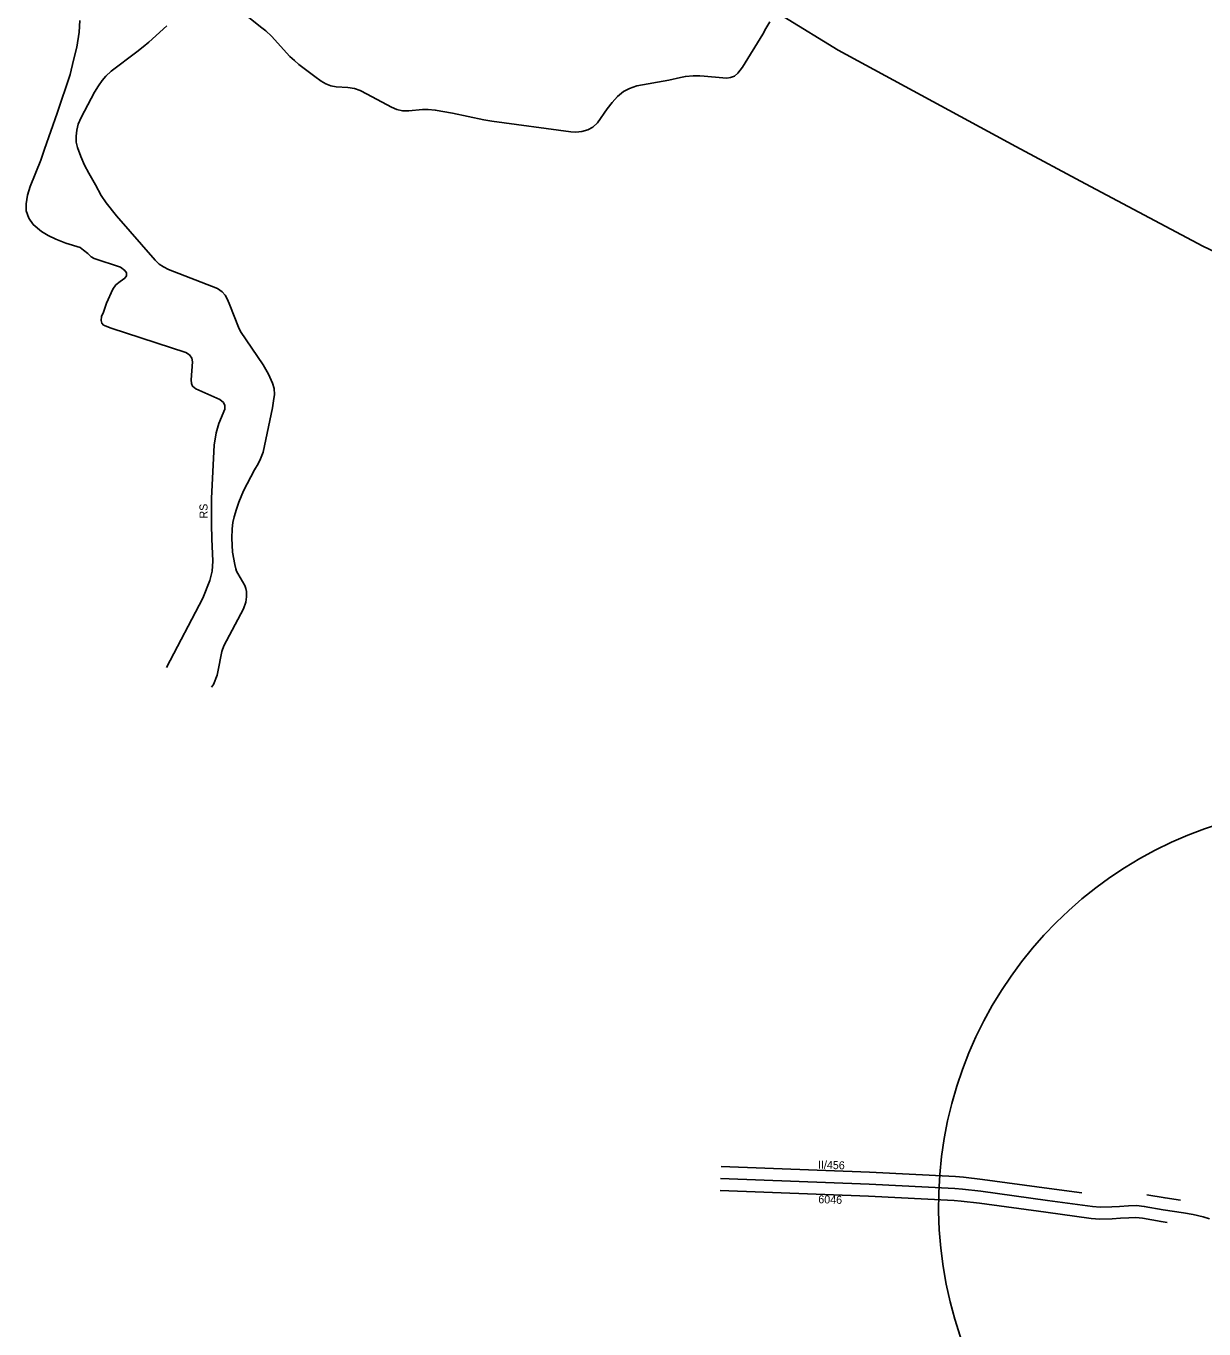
# Model space of a CAD drawing. Extents: x -546703 to -534152, y -1046534 to -1035676.
# Drawn here: x -545023 to -543551, y -1040697 to -1039069 of the extents above; entities that cross this region are included whole.
import ezdxf

# ---------------------------------------------------------------- set-up
doc = ezdxf.new("R2010")
doc.units = 0
for name, color, linetype in [('Vrstva 11', 7, 'Continuous'), ('Vrstva 17', 7, 'Continuous'), ('Vrstva 22', 7, 'Continuous'), ('Vrstva 26', 7, 'Continuous'), ('Vrstva 3', 7, 'Continuous')]:
    doc.layers.add(name, color=color, linetype=linetype)

msp = doc.modelspace()

# ---------------------------------------------------------------- linework, layer by layer
at = {"layer": 'Vrstva 11'}
for points in [[(-544093.2, -1039063.3), (-544098.2, -1039071.8), (-544102, -1039078.9), (-544127.3, -1039120.2), (-544133.1, -1039127.7), (-544137.4, -1039131.3), (-544142.2, -1039133.1), (-544147.1, -1039133.8), (-544151.9, -1039133.5), (-544175.2, -1039131.2), (-544180.8, -1039130.9), (-544189.2, -1039131), (-544198.6, -1039131.7), (-544204.8, -1039132.9), (-544219.4, -1039136.2), (-544259.5, -1039143.5), (-544268.4, -1039146.6), (-544275.9, -1039150.7), (-544283.5, -1039156.9), (-544290.2, -1039164.3), (-544296.6, -1039172.3), (-544308.6, -1039189.6), (-544314.3, -1039195), (-544320.5, -1039198.5), (-544328.2, -1039200.7), (-544335.6, -1039201.2), (-544342, -1039200.8), (-544440.4, -1039187.8), (-544450.4, -1039186), (-544489.5, -1039177.8), (-544511.2, -1039173.8), (-544519.9, -1039173), (-544527.3, -1039173.2), (-544544.2, -1039174.8), (-544552.1, -1039174.6), (-544559.3, -1039172.9), (-544565.9, -1039170.3), (-544596.2, -1039154), (-544605.1, -1039149.4), (-544612, -1039146.9), (-544620.5, -1039145.6), (-544634.9, -1039144.8), (-544641.6, -1039143.3), (-544648.1, -1039140.8), (-544654, -1039137.7), (-544661.6, -1039132), (-544681.6, -1039116.9), (-544687, -1039112), (-544693.1, -1039106.7), (-544715.9, -1039081.6), (-544723.1, -1039074.8), (-544729.4, -1039069.9), (-544784.9, -1039024.7)], [(-543511.8, -1039362.9), (-543552.3, -1039343.9), (-543698.9, -1039265.8), (-543785.9, -1039219.3), (-544008, -1039098.7), (-544075.9, -1039057.3)], [(-544846.8, -1039068.5), (-544869.2, -1039089), (-544876.1, -1039094.9), (-544884.3, -1039100.9), (-544916, -1039125.1), (-544922.7, -1039131.3), (-544927.6, -1039136.9), (-544932.2, -1039143.6), (-544936.8, -1039151.5), (-544953.8, -1039182.9), (-544957.4, -1039191.2), (-544959.2, -1039199), (-544959.9, -1039206.5), (-544959.8, -1039214), (-544958.4, -1039220.6), (-544953.9, -1039231.8), (-544949.3, -1039242.4), (-544944, -1039252.4), (-544935.9, -1039267.2), (-544928.5, -1039280.4), (-544922.4, -1039289.5), (-544909.5, -1039306), (-544861.2, -1039361.4), (-544856.2, -1039366.1), (-544850.7, -1039369.7), (-544844.4, -1039372.8), (-544783.3, -1039396.8), (-544777.5, -1039400.7), (-544773.8, -1039405.2), (-544770.8, -1039410.6), (-544767.8, -1039417.6), (-544757.1, -1039444.8), (-544754.7, -1039450.6), (-544747.7, -1039460.8), (-544726.1, -1039491.9), (-544719.6, -1039503.7), (-544714.4, -1039515), (-544712.4, -1039521.6), (-544712.2, -1039528.9), (-544713.5, -1039537.2), (-544714.8, -1039545.6), (-544726.2, -1039601.2), (-544729.7, -1039609.5), (-544732.7, -1039615.8), (-544736.9, -1039623.4), (-544750.8, -1039649.3), (-544756.5, -1039663.7), (-544759.7, -1039672.5), (-544762.7, -1039681.9), (-544764.2, -1039688.9), (-544764.9, -1039697), (-544765.2, -1039708.5), (-544764.7, -1039726.2), (-544761.7, -1039741.4), (-544760.6, -1039746.9), (-544759.5, -1039749.9), (-544758, -1039752.8), (-544749, -1039767.7), (-544747.8, -1039771.4), (-544747.2, -1039775.2), (-544747.2, -1039781.7), (-544748, -1039788.5), (-544750.9, -1039796.7), (-544775.4, -1039843.1), (-544778.1, -1039850.1), (-544782.9, -1039875.6), (-544783.6, -1039879.6), (-544788.5, -1039891.4), (-544790.7, -1039894.8)]]:
    msp.add_lwpolyline(points, dxfattribs=at)
at = {"layer": 'Vrstva 17'}
for points in [[(-544154.2, -1040493.6), (-543968.6, -1040500.9), (-543861.1, -1040506.2), (-543851.1, -1040506.9), (-543827.6, -1040509.7), (-543744.3, -1040521.1), (-543703.5, -1040526.7)], [(-543596.7, -1040563.7), (-543604.3, -1040562.5), (-543627.6, -1040558.4), (-543635.8, -1040557.4), (-543644.6, -1040557.6), (-543655.3, -1040558.4), (-543665.4, -1040559.1), (-543680.9, -1040559.3), (-543691.7, -1040558.6), (-543748.4, -1040550.8), (-543831.4, -1040539.4), (-543854, -1040536.8), (-543863, -1040536.1), (-543969.9, -1040530.9), (-544155.4, -1040523.5)], [(-543622.1, -1040528.9), (-543599.5, -1040532.9), (-543580, -1040535.8)]]:
    msp.add_lwpolyline(points, dxfattribs=at)
at = {"layer": 'Vrstva 22'}
for points in [[(-544846.9, -1039870), (-544801.7, -1039783.6), (-544792.7, -1039761.5), (-544790.1, -1039749.9), (-544789.2, -1039737.4), (-544790.5, -1039709.5), (-544790.8, -1039691.5), (-544790.8, -1039658.7), (-544787.3, -1039592.6), (-544785, -1039577.1), (-544781.8, -1039565.3), (-544774.1, -1039547.6), (-544774.1, -1039542.8), (-544776, -1039538.9), (-544780.2, -1039535.4), (-544810.4, -1039521.9), (-544814.5, -1039518.7), (-544815.8, -1039515.2), (-544816.1, -1039510.7), (-544814.5, -1039488.2), (-544815.5, -1039483.7), (-544818.4, -1039479.5), (-544822.9, -1039476.6), (-544916, -1039446.1), (-544925.6, -1039442.3), (-544927.8, -1039440), (-544928.8, -1039436.8), (-544928.1, -1039431.7), (-544925.9, -1039426.2), (-544922.1, -1039415), (-544914, -1039397.6), (-544910.5, -1039392.2), (-544905, -1039388), (-544899.3, -1039383.8), (-544897, -1039380.9), (-544897, -1039377.1), (-544898.9, -1039374.2), (-544904.7, -1039370), (-544937.5, -1039359.1), (-544941, -1039357.2), (-544945.2, -1039353), (-544950.6, -1039348.8), (-544955.1, -1039345.6), (-544972.8, -1039340.1), (-544985.3, -1039335), (-544994.9, -1039330.5), (-545003.2, -1039325.4), (-545013.8, -1039316.7), (-545019, -1039308.7), (-545022.2, -1039299.7), (-545022.5, -1039290.7), (-545020.9, -1039280.1), (-545017.4, -1039269.2), (-545004.2, -1039236.4), (-544999.4, -1039222.6), (-544983.7, -1039177.7), (-544967.6, -1039129.5), (-544963.1, -1039111.5), (-544959, -1039095.1), (-544956.1, -1039076.5), (-544955.4, -1039061.7)], [(-544154.8, -1040508.6), (-543969.3, -1040515.9), (-543862, -1040521.2), (-543852.6, -1040521.9), (-543829.5, -1040524.6), (-543746.4, -1040536), (-543690.2, -1040543.7), (-543680.6, -1040544.3), (-543666, -1040544.1), (-543656.3, -1040543.5), (-543645.3, -1040542.6), (-543635.1, -1040542.4), (-543625.4, -1040543.6), (-543601.9, -1040547.7), (-543576.4, -1040551.5), (-543564.4, -1040553.6), (-543551.7, -1040556.7), (-543543.7, -1040559)]]:
    msp.add_lwpolyline(points, dxfattribs=at)
at = {"layer": 'Vrstva 26'}
msp.add_arc((-543382.4, -1040542.8), 500, 99.089, 344.2283, dxfattribs=at)
at = {"layer": 'Vrstva 3'}
msp.add_lwpolyline([(-544154.8, -1040508.6), (-543969.3, -1040515.9), (-543862, -1040521.2), (-543852.6, -1040521.9), (-543829.5, -1040524.6), (-543746.4, -1040536), (-543690.2, -1040543.7), (-543680.6, -1040544.3), (-543666, -1040544.1), (-543656.3, -1040543.5), (-543645.3, -1040542.6), (-543635.1, -1040542.4), (-543625.4, -1040543.6), (-543601.9, -1040547.7), (-543576.4, -1040551.5), (-543564.4, -1040553.6), (-543551.7, -1040556.7), (-543543.7, -1040559)], dxfattribs=at)

# ---------------------------------------------------------------- texts
at = {"layer": 'Vrstva 22'}
for s, rotation, p in [('RS', 90, (-544795.8, -1039684.1)), ('6046', 358.3468, (-544032.8, -1040539.5))]:
    msp.add_text(s, height=10, rotation=rotation, dxfattribs=at).set_placement(p)
at = {"layer": 'Vrstva 3'}
msp.add_text('II/456', height=10, rotation=358.3468, dxfattribs=at).set_placement((-544033.2, -1040496.3))

doc.saveas('drawing.dxf')
